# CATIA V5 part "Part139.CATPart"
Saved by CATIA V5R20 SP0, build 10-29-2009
Part number: DFA 084700-2 comprimido
Revision: ANY
Definition: UNKNOWN
Nomenclature: DFA 084700-2 comprimido
Source: Unknown
Bounding box of the stored display mesh (mm): x -2.45 to 2.45, y 0 to 4.72, z -2.45 to 2.45
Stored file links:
  C:\Users\Utente\Desktop\IO LAVORO\3D X SITO CF\CUMSA\3D files FA\FA 084712-21\Part139.CATPart

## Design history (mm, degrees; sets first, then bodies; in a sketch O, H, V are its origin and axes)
Body1 "Cortar-Extruir1" (main body)
  Solid1: solid without history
